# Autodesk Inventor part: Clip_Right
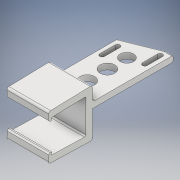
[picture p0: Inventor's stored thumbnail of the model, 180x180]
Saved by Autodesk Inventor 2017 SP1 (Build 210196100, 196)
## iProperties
Created: 2017-10
Part Number: Clip_Right
Material: ABS Plastic
Document SubType Name: Modeling
Designer: Nick
Density: 1.06 g/cm^3
Appearance: Smooth - White
Mass: 8.33269 g
Surface Area: 88.2688 cm^2
Volume: 7.86103 cm^3
Created: 2017-12
Part Number: Clip_Right_3DPrint
Material: Generic
Density: 1 g/cm^3
Appearance: Default
Author: Nick
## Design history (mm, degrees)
sketch "Sketch1"
  geometry: L1 (0, 0)-(0, -17.733); L2 (-4.8, 0)-(-4.8, -12.8); L3 (-32.521, -16.844)-(0, -17.733); L4 (-4.8, 0)-(0, 0); L5 (-32.521, -16.844)-(-32.335, -10.046); L6 (-32.335, -10.046)-(-30.336, -10.101); L7 (-30.39, -12.1)-(-30.336, -10.101); L8 (-4.8, -12.8)-(-30.39, -12.1); 3 further points; 1 other entity
  constraints: 16 end point, 3 perpendicular, 2 coincident, 1 horizontal, 1 parallel, 1 vertical, 2 other
  dimensions: "d0" = 4.8 distance between parallel lines of L1 L2; "d6" = 12.8 distance of L2.start L2.end; "d7" = 2 distance of L7.start L6.end; "d8" = 25.6 distance of L7.start L2.end (= 2 x d6); "d9" = 2 distance of L5.end L6.end; "d13" = 4.8 distance between parallel lines of L3 L8; "d14" = 0.7 vertical distance of L7.start L2.end; "d20" = 88.4331 deg angle of L3 L1 (derived)
extrude "Clamp half" new body sketch "Sketch1" distance "d10" = 31; taper "d11" = 0 deg
mirror "Clamp Mirror"
workplane "Work Plane1"
sketch "Sketch2"
  geometry: L1 (31, 60)-(0, 60); L2 (0, 60)-(0, 0); L3 (0, 0)-(31, 0); L4 (31, 0)-(31, 60); L5 (0, 0)-(31, 0) reference; L6 (28, 57)-(24.5, 57); L7 (24.5, 57)-(24.5, 55.25); L8 (24.5, 42)-(28, 42); L9 (28, 42)-(28, 43.75); L10 (28, 55.25)-(28, 57); L11 (24.5, 55.25)-(24.5, 43.75); L12 (24.5, 43.75)-(24.5, 42); L13 (28, 43.75)-(28, 55.25); L14 (15.5, 60)-(15.5, 0); L15 (2.8, 32)-(2.8, 33.75); L16 (2.8, 33.75)-(2.8, 45.25); L17 (2.8, 45.25)-(2.8, 47); L18 (6.3, 33.75)-(6.3, 32); L19 (6.3, 47)-(6.3, 45.25); L20 (6.3, 45.25)-(6.3, 33.75); A1 r 1.75 centre (26.25, 55.25) between (28, 55.25) and (24.5, 55.25); A2 r 1.75 centre (26.25, 43.75) between (24.5, 43.75) and (28, 43.75); A3 r 1.75 centre (4.55, 33.75) between (2.8, 33.75) and (6.3, 33.75); A4 r 1.75 centre (4.55, 45.25) between (6.3, 45.25) and (2.8, 45.25); 6 further points; 2 other entities
  constraints: 38 end point, 22 point on circle, 13 parallel, 6 vertical, 4 centre point, 4 horizontal alignment, 4 midpoint, 4 perpendicular, 4 point on line, 2 horizontal, 1 tangent, 1 vertical alignment, 8 other
  dimensions: "d16" = 31 distance of L1.start L1.end; "d17" = 60 distance of L3.end L1.start; "d21" = 3.5 distance of L6.start L6.end; "d22" = 15 distance of L6.end L8.start; "d23" = 1.75 radius of A1 (= 0.5 x d21); "d24" = 3 distance between parallel lines of L4 L9; "d25" = 3 distance from line of L1 L6.start; "d26" = 1.75 radius of A2 (= d23); "d27" = 18.2 distance between parallel lines of L11 L20; "d30" = 1.75 radius of A4 (= d23); "d31" = 1.75 radius of A3 (= d23); "d34" = 3.5 distance of L16.end L19.end (= d21); "d36" = 13 distance from line of L1 L17.end; "d71" = 2.8 distance between parallel lines of L2 L16 (derived)
extrude "Extrusion4" join sketch "Sketch2" distance "d28" = 4.4; taper "d29" = 0 deg
fillet "Fillet1" dims "d37" = 2
fillet "Fillet2" dims "d38" = 1.5
sketch "Sketch6"
  geometry: L1 (2.6, 17)-(-14.4, 0); L2 (2.6, 0)-(2.6, 60) reference; L3 (2.6, 0)-(-16.192, 0) reference; 1 further point
  constraints: 2 end point, 2 point on line
  dimensions: "d66" = 45 deg angle of L2 L1; "d67" = 17 distance of L2.start L1.end
extrude "Support" join sketch "Sketch6" distance "d68" = 2; taper "d69" = 0 deg
sketch "Sketch5"
  geometry: L1 (0, 0)-(-31, 0) reference; C1 r 5.5 at (-15.5, 11.719); C2 r 5.5 at (-15.5, 26.719); C3 r 5 at (-15.5, 41.219); A1 r 1.75 centre (-4.55, 33.75) between (-6.3, 33.75) and (-2.8, 33.75) reference; 4 further points
  constraints: 4 midpoint, 3 centre point, 2 vertical alignment
  dimensions: "d51" = 11 diameter of C1; "d52" = 11 diameter of C2; "d53" = 5.7627 dimension on C2 A1 (derived); "d54" = 10 diameter of C3; "d55" = 4 dimension on C2 C3; "d56" = 4 dimension on C1 C2
extrude "Extrusion7" cut sketch "Sketch5" stored distance "d57" = 10; taper "d58" = 0 deg
chamfer "Chamfer1" distance "d59" = 1; stored, may be unused: second distance "d60" = 2, angle "d61" = 45 deg
fillet "Fillet4" dims "d62" = 1
chamfer "Chamfer2" distance "d63" = 10; stored, may be unused: second distance "d64" = 25, angle "d65" = 45 deg
fillet "Fillet5" dims "d70" = 1
body "Solid2"
other parameters: "d15" = 7, "sa_0" = 0, "sa_1" = 0, "sa_2" = 50000, "sa_3" = 0, "sa_4" = -390.625, "sa_5" = 19996.18494
